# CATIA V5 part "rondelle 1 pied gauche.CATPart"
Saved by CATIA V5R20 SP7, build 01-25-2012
Part number: rondelle 1 pied gauche
Bounding box of the stored display mesh (mm): x 19.398 to 32.022, y -79 to -65, z 34.427 to 42.293
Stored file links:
  F:\Travaux\Modélisations\CFAO_2011\CFAO_2011_MMS\CFAO_2011_MMS_DONE\CFAO_2011_MMS_jboiteux\Catia\rondelle 1 pied gauche.CATPart
  U:\finthinkmotion\stepper.CATProduct
  F:\Travaux\Modélisations\CFAO_2011\CFAO_2011_MMS\CFAO_2011_MMS_DONE\CFAO_2011_MMS_jboiteux\Catia\entretoise pied gauche.CATPart
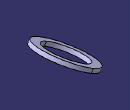
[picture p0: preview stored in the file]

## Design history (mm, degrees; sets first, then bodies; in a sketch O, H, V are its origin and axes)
Set1
  DatumSurface1: linked copy from another document
Body1 (main body)
  Sketch1 on face of DatumSurface1, origin (-9.9328, 0, 17.204), H (0, 1, 0), V (0.866, 0, 0.5)
    projected circle E1 centre (-72, 41.4454) radius 7 from edge of DatumSurface1
    projected circle E2 centre (-72, 41.4454) radius 5 from edge of DatumSurface1
  Pad1: profile Sketch1, direction (-0.5, 0, 0.866), length 1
